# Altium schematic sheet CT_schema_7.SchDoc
size 253 x 245 mm
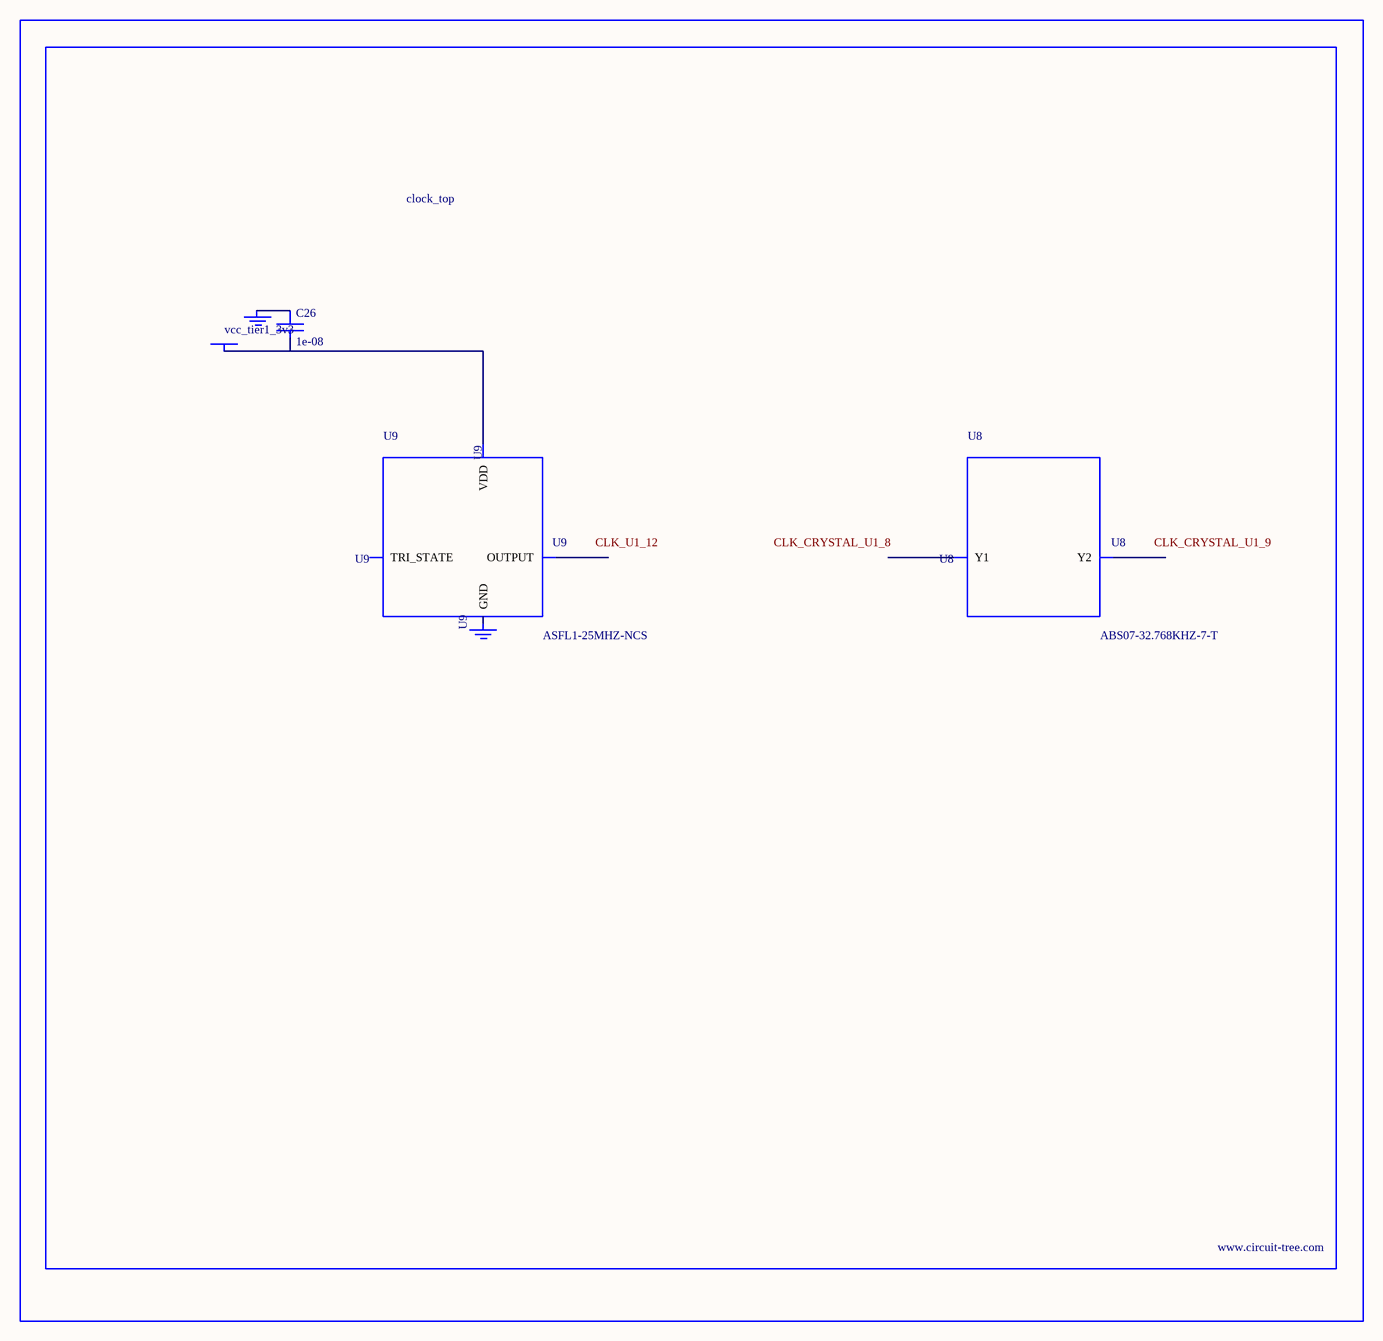
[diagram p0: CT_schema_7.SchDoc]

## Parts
BORDER6  (no value)
C26  1e-08  [C0402]
GND_INSTANCE_6_0  (no value)
GND_INSTANCE_6_1  (no value)
POWER_INSTANCE_6_0  vcc_tier1_3v3
U8  ABS07-32.768KHZ-7-T  [ABS07-32.768KHZ-7-T]
U9  ASFL1-25MHZ-NCS  [ASFL1]

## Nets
NetC26_1: C26.1 GND_INSTANCE_6_0.0(GND)
NetC26_2: C26.2 POWER_INSTANCE_6_0.0(PWR) U9.4(VDD)

Not connected (* = marked no-connect by the designer): GND_INSTANCE_6_1 0(GND); U8 1(Y1) 2(Y2); U9 1(TRI_STATE) 2(GND) 3(OUTPUT)

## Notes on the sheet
- Labels drawn without touching a wire or pin: CLK_CRYSTAL_U1_8, CLK_CRYSTAL_U1_9, CLK_U1_12

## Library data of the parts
BORDER6 = BORDER_PAGE6
C26 = C0402C103K3RAC
GND_INSTANCE_6_0 GND_INSTANCE_6_1 = GND
POWER_INSTANCE_6_0 = PWR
